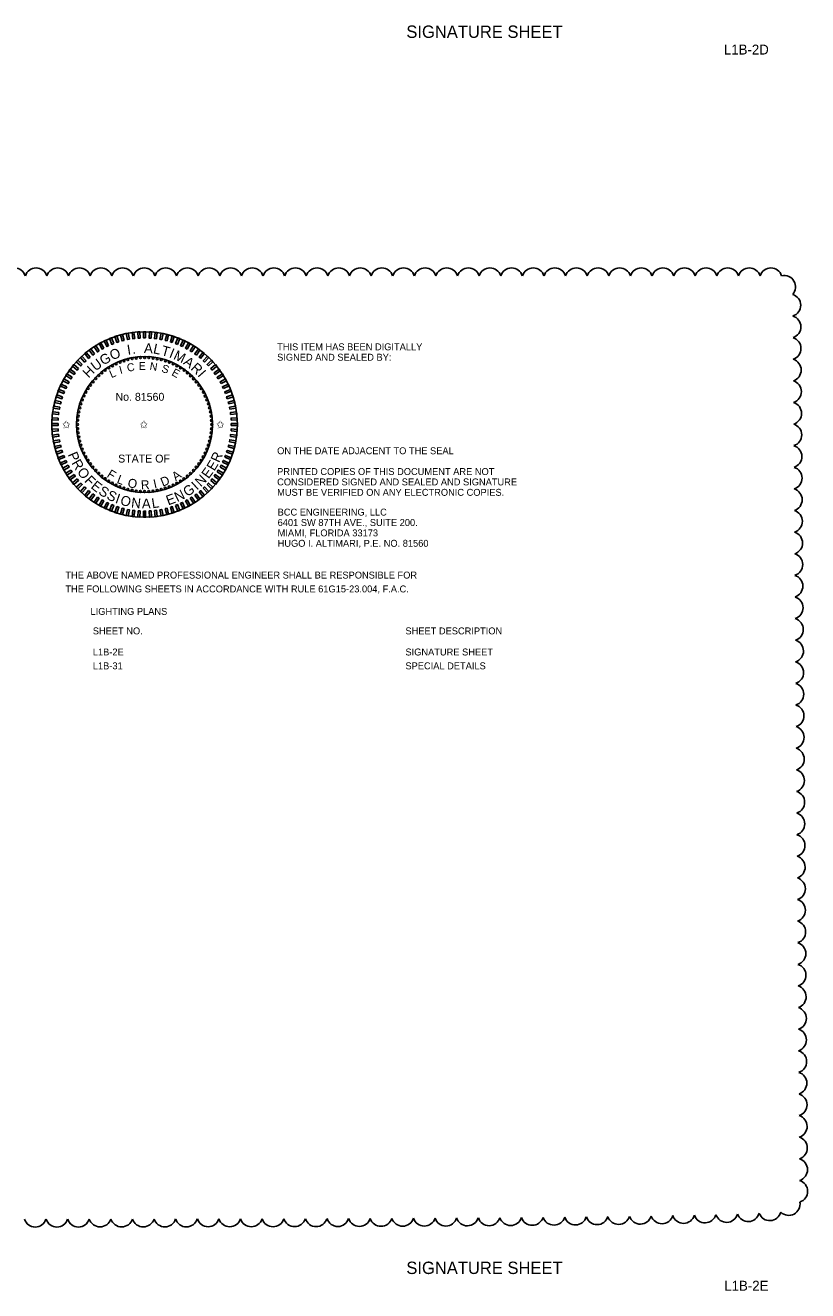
# Model space of a CAD drawing. Extents: x -811.2 to -795, y -2307.6 to -2235.1.
# Drawn here: x -803.05 to -795.14, y -2307.64 to -2294.86 of the extents above; entities that cross this region are included whole.
import ezdxf

# ---------------------------------------------------------------- set-up
doc = ezdxf.new("R2010")
doc.units = 0
for name, color, linetype in [('Cloud_dp', 7, 'Continuous'), ('Logo_dp', 7, 'Continuous'), ('NonPlottingEle_dp', 7, 'Continuous'), ('TeleMisc', 7, 'Continuous'), ('TextDetails', 7, 'Continuous'), ('TextMisc', 7, 'Continuous')]:
    doc.layers.add(name, color=color, linetype=linetype)

msp = doc.modelspace()

# ---------------------------------------------------------------- linework, layer by layer
at = {"layer": 'Cloud_dp'}
for centre, start, end in [((-803.157, -2297.421), 17.5, 162.5), ((-802.939, -2297.421), 17.5, 162.5), ((-802.721, -2297.421), 17.5, 162.5), ((-802.502, -2297.421), 17.5, 162.5), ((-802.284, -2297.421), 17.5, 162.5), ((-802.066, -2297.421), 17.5, 162.5), ((-801.847, -2297.421), 17.5, 162.5), ((-801.629, -2297.421), 17.5, 162.5), ((-801.411, -2297.421), 17.5, 162.5), ((-801.192, -2297.421), 17.5, 162.5), ((-800.974, -2297.421), 17.5, 162.5), ((-800.756, -2297.421), 17.5, 162.5), ((-800.537, -2297.421), 17.5, 162.5), ((-800.319, -2297.421), 17.5, 162.5), ((-800.101, -2297.421), 17.5, 162.5), ((-799.882, -2297.421), 17.5, 162.5), ((-799.664, -2297.421), 17.5, 162.5), ((-799.446, -2297.421), 17.5, 162.5), ((-799.227, -2297.421), 17.5, 162.5), ((-799.009, -2297.421), 17.5, 162.5), ((-798.791, -2297.421), 17.5, 162.5), ((-798.572, -2297.421), 17.5, 162.5), ((-798.354, -2297.421), 17.5, 162.5), ((-798.136, -2297.421), 17.5, 162.5), ((-797.917, -2297.421), 17.5, 162.5), ((-797.699, -2297.421), 17.5, 162.5), ((-797.481, -2297.421), 17.5, 162.5), ((-797.262, -2297.421), 17.5, 162.5), ((-797.044, -2297.421), 17.5, 162.5), ((-796.826, -2297.421), 17.5, 162.5), ((-796.607, -2297.421), 17.5, 162.5), ((-796.389, -2297.421), 17.5, 162.5), ((-796.171, -2297.421), 17.5, 162.5), ((-795.952, -2297.421), 17.5, 162.5), ((-795.734, -2297.421), 17.5, 162.5), ((-795.516, -2297.421), 17.5, 162.5), ((-795.381, -2297.498), 318.1116, 103.1116), ((-795.329, -2297.684), 287.9529, 72.9529), ((-795.327, -2297.902), 287.9529, 72.9529), ((-795.326, -2298.121), 287.9529, 72.9529), ((-795.324, -2298.339), 287.9529, 72.9529), ((-795.322, -2298.557), 287.9529, 72.9529), ((-795.32, -2298.776), 287.9529, 72.9529), ((-795.319, -2298.994), 287.9529, 72.9529), ((-795.317, -2299.212), 287.9529, 72.9529), ((-795.315, -2299.431), 287.9529, 72.9529), ((-795.314, -2299.649), 287.9529, 72.9529), ((-795.312, -2299.867), 287.9529, 72.9529), ((-795.31, -2300.086), 287.9529, 72.9529), ((-795.308, -2300.304), 287.9529, 72.9529), ((-795.307, -2300.522), 287.9529, 72.9529), ((-795.305, -2300.741), 287.9529, 72.9529), ((-795.303, -2300.959), 287.9529, 72.9529), ((-795.301, -2301.177), 287.9529, 72.9529), ((-795.3, -2301.395), 287.9529, 72.9529), ((-795.298, -2301.614), 287.9529, 72.9529), ((-795.296, -2301.832), 287.9529, 72.9529), ((-795.295, -2302.05), 287.9529, 72.9529), ((-795.293, -2302.269), 287.9527, 72.9527), ((-795.291, -2302.487), 287.9524, 72.9524), ((-795.289, -2302.705), 287.9521, 72.9521), ((-795.288, -2302.924), 287.9519, 72.9519), ((-795.286, -2303.142), 287.9515, 72.9515), ((-795.284, -2303.36), 287.9512, 72.9512), ((-795.282, -2303.579), 287.9508, 72.9508), ((-795.281, -2303.797), 287.9504, 72.9504), ((-795.279, -2304.015), 287.9499, 72.9499), ((-795.277, -2304.234), 287.9494, 72.9494), ((-795.276, -2304.452), 287.9488, 72.9488), ((-795.274, -2304.67), 287.9481, 72.9481), ((-795.272, -2304.889), 287.9473, 72.9473), ((-795.271, -2305.107), 287.9464, 72.9464), ((-795.269, -2305.325), 287.9452, 72.9452), ((-795.267, -2305.543), 287.9438, 72.9438), ((-795.265, -2305.762), 287.9419, 72.9419), ((-795.264, -2305.98), 287.9394, 72.9394), ((-795.262, -2306.198), 287.9355, 72.9355), ((-795.26, -2306.417), 287.9288, 72.9288), ((-795.259, -2306.635), 287.9106, 72.9106), ((-795.336, -2306.765), 225.4798, 10.4798), ((-802.948, -2306.882), 197.5011, 342.5011), ((-802.729, -2306.882), 197.5111, 342.5111), ((-802.511, -2306.882), 197.522, 342.522), ((-802.293, -2306.881), 197.5335, 342.5335), ((-802.074, -2306.881), 197.5456, 342.5456), ((-801.856, -2306.881), 197.5582, 342.5582), ((-801.638, -2306.881), 197.5715, 342.5715), ((-801.42, -2306.881), 197.5855, 342.5855), ((-801.201, -2306.88), 197.6002, 342.6002), ((-800.983, -2306.88), 197.6157, 342.6157), ((-800.765, -2306.879), 197.6322, 342.6322), ((-800.546, -2306.879), 197.6497, 342.6497), ((-800.328, -2306.878), 197.6683, 342.6683), ((-800.11, -2306.878), 197.6881, 342.6881), ((-799.891, -2306.877), 197.7093, 342.7093), ((-799.673, -2306.876), 197.732, 342.732), ((-799.455, -2306.875), 197.7565, 342.7565), ((-799.236, -2306.874), 197.7829, 342.7829), ((-799.018, -2306.873), 197.8116, 342.8116), ((-798.8, -2306.872), 197.8429, 342.8429), ((-798.582, -2306.87), 197.8771, 342.8771), ((-798.363, -2306.869), 197.9149, 342.9149), ((-798.145, -2306.867), 197.9569, 342.9569), ((-797.927, -2306.865), 198.0039, 343.0039), ((-797.708, -2306.863), 198.0569, 343.0569), ((-797.49, -2306.861), 198.1174, 343.1174), ((-797.272, -2306.858), 198.1874, 343.1874), ((-797.054, -2306.856), 198.2696, 343.2696), ((-796.835, -2306.853), 198.368, 343.368), ((-796.617, -2306.849), 198.4888, 343.4888), ((-796.399, -2306.845), 198.642, 343.642), ((-796.181, -2306.84), 198.8454, 343.8454), ((-795.963, -2306.835), 199.1345, 344.1345), ((-795.745, -2306.827), 199.5943, 344.5943), ((-795.527, -2306.818), 200.5167, 345.5167)]:
    msp.add_arc(centre, 0.114, start, end, dxfattribs=at)
at = {"layer": 'TextDetails'}
for radius in [0.937, 0.687]:
    msp.add_circle((-801.843, -2298.889), radius, dxfattribs=at)
at = {"layer": 'TextMisc'}
for p, q in [((-801.853, -2299.826), (-801.853, -2299.763)), ((-801.843, -2299.826), (-801.843, -2299.763)), ((-801.833, -2299.826), (-801.833, -2299.763))]:
    msp.add_line(p, q, dxfattribs=at)
for points in [[(-801.997, -2298.028), (-802.016, -2298.031), (-802.028, -2297.97), (-802.008, -2297.966)], [(-801.942, -2298.02), (-801.962, -2298.022), (-801.97, -2297.96), (-801.95, -2297.958)], [(-801.887, -2298.015), (-801.908, -2298.016), (-801.912, -2297.954), (-801.891, -2297.953)], [(-801.833, -2298.014), (-801.853, -2298.014), (-801.853, -2297.952), (-801.833, -2297.952)], [(-801.778, -2298.016), (-801.798, -2298.015), (-801.794, -2297.953), (-801.774, -2297.954)], [(-801.723, -2298.022), (-801.743, -2298.02), (-801.735, -2297.958), (-801.715, -2297.96)], [(-801.669, -2298.032), (-801.689, -2298.028), (-801.677, -2297.966), (-801.657, -2297.97)], [(-802.303, -2298.145), (-802.32, -2298.156), (-802.353, -2298.103), (-802.336, -2298.092)], [(-802.255, -2298.117), (-802.273, -2298.127), (-802.303, -2298.072), (-802.285, -2298.063)], [(-802.206, -2298.093), (-802.224, -2298.102), (-802.251, -2298.045), (-802.232, -2298.037)], [(-802.155, -2298.072), (-802.174, -2298.079), (-802.197, -2298.021), (-802.178, -2298.014)], [(-802.103, -2298.054), (-802.122, -2298.06), (-802.142, -2298.001), (-802.123, -2297.994)], [(-802.05, -2298.039), (-802.07, -2298.044), (-802.085, -2297.984), (-802.066, -2297.979)], [(-801.615, -2298.044), (-801.635, -2298.039), (-801.619, -2297.979), (-801.6, -2297.984)], [(-801.563, -2298.06), (-801.582, -2298.054), (-801.563, -2297.994), (-801.543, -2298.001)], [(-801.511, -2298.079), (-801.53, -2298.072), (-801.507, -2298.014), (-801.488, -2298.021)], [(-801.461, -2298.102), (-801.479, -2298.093), (-801.453, -2298.037), (-801.434, -2298.045)], [(-801.412, -2298.127), (-801.43, -2298.117), (-801.4, -2298.063), (-801.382, -2298.073)], [(-801.365, -2298.156), (-801.382, -2298.145), (-801.349, -2298.092), (-801.332, -2298.103)], [(-802.434, -2298.244), (-802.449, -2298.258), (-802.491, -2298.213), (-802.477, -2298.199)], [(-802.392, -2298.208), (-802.408, -2298.221), (-802.448, -2298.173), (-802.432, -2298.16)], [(-802.349, -2298.175), (-802.365, -2298.187), (-802.402, -2298.137), (-802.385, -2298.125)], [(-801.32, -2298.187), (-801.337, -2298.175), (-801.3, -2298.125), (-801.284, -2298.137)], [(-801.277, -2298.221), (-801.293, -2298.208), (-801.253, -2298.16), (-801.238, -2298.173)], [(-801.237, -2298.258), (-801.251, -2298.244), (-801.208, -2298.199), (-801.194, -2298.213)], [(-802.544, -2298.366), (-802.556, -2298.383), (-802.607, -2298.346), (-802.595, -2298.33)], [(-802.51, -2298.323), (-802.523, -2298.339), (-802.571, -2298.299), (-802.558, -2298.284)], [(-802.473, -2298.283), (-802.487, -2298.297), (-802.533, -2298.255), (-802.519, -2298.24)], [(-801.198, -2298.297), (-801.212, -2298.283), (-801.166, -2298.24), (-801.153, -2298.255)], [(-801.162, -2298.339), (-801.175, -2298.324), (-801.127, -2298.284), (-801.114, -2298.299)], [(-801.129, -2298.383), (-801.141, -2298.367), (-801.09, -2298.33), (-801.079, -2298.346)], [(-802.63, -2298.507), (-802.638, -2298.525), (-802.695, -2298.499), (-802.686, -2298.481)], [(-802.604, -2298.458), (-802.614, -2298.476), (-802.669, -2298.446), (-802.659, -2298.428)], [(-802.576, -2298.412), (-802.587, -2298.429), (-802.639, -2298.395), (-802.628, -2298.378)], [(-801.099, -2298.429), (-801.11, -2298.412), (-801.057, -2298.378), (-801.046, -2298.395)], [(-801.071, -2298.476), (-801.081, -2298.459), (-801.026, -2298.429), (-801.017, -2298.446)], [(-801.047, -2298.526), (-801.056, -2298.507), (-800.999, -2298.481), (-800.99, -2298.499)], [(-802.671, -2298.609), (-802.678, -2298.628), (-802.737, -2298.609), (-802.731, -2298.59)], [(-802.652, -2298.557), (-802.66, -2298.576), (-802.718, -2298.553), (-802.71, -2298.534)], [(-801.026, -2298.576), (-801.033, -2298.558), (-800.975, -2298.535), (-800.968, -2298.553)], [(-801.008, -2298.628), (-801.014, -2298.609), (-800.955, -2298.59), (-800.948, -2298.609)], [(-802.7, -2298.715), (-802.704, -2298.735), (-802.765, -2298.723), (-802.761, -2298.703)], [(-802.687, -2298.661), (-802.692, -2298.681), (-802.753, -2298.665), (-802.748, -2298.646)], [(-800.993, -2298.681), (-800.998, -2298.662), (-800.938, -2298.646), (-800.932, -2298.666)], [(-800.982, -2298.735), (-800.985, -2298.715), (-800.924, -2298.703), (-800.92, -2298.723)], [(-802.715, -2298.824), (-802.716, -2298.844), (-802.779, -2298.84), (-802.777, -2298.82)], [(-802.709, -2298.769), (-802.712, -2298.789), (-802.774, -2298.781), (-802.771, -2298.761)], [(-800.974, -2298.789), (-800.976, -2298.769), (-800.914, -2298.761), (-800.912, -2298.781)], [(-800.969, -2298.844), (-800.97, -2298.824), (-800.908, -2298.82), (-800.907, -2298.84)], [(-802.717, -2298.879), (-802.717, -2298.899), (-802.78, -2298.899), (-802.78, -2298.879)], [(-802.716, -2298.934), (-802.715, -2298.954), (-802.777, -2298.958), (-802.779, -2298.937)], [(-802.712, -2298.988), (-802.709, -2299.008), (-802.771, -2299.016), (-802.774, -2298.996)], [(-800.976, -2299.009), (-800.974, -2298.989), (-800.912, -2298.996), (-800.914, -2299.016)], [(-800.97, -2298.954), (-800.969, -2298.934), (-800.907, -2298.938), (-800.908, -2298.958)], [(-800.968, -2298.899), (-800.968, -2298.879), (-800.906, -2298.879), (-800.906, -2298.899)], [(-802.704, -2299.043), (-802.7, -2299.063), (-802.761, -2299.074), (-802.765, -2299.054)], [(-802.692, -2299.096), (-802.687, -2299.116), (-802.748, -2299.132), (-802.753, -2299.112)], [(-800.998, -2299.116), (-800.993, -2299.097), (-800.933, -2299.112), (-800.938, -2299.132)], [(-800.985, -2299.063), (-800.982, -2299.043), (-800.92, -2299.055), (-800.924, -2299.074)], [(-802.678, -2299.149), (-802.671, -2299.169), (-802.731, -2299.188), (-802.737, -2299.169)], [(-802.66, -2299.201), (-802.652, -2299.22), (-802.71, -2299.243), (-802.718, -2299.224)], [(-802.638, -2299.252), (-802.63, -2299.27), (-802.686, -2299.297), (-802.695, -2299.279)], [(-801.056, -2299.27), (-801.047, -2299.252), (-800.991, -2299.279), (-800.999, -2299.297)], [(-801.033, -2299.22), (-801.026, -2299.201), (-800.968, -2299.224), (-800.975, -2299.243)], [(-801.014, -2299.169), (-801.008, -2299.15), (-800.948, -2299.169), (-800.955, -2299.188)], [(-802.614, -2299.301), (-802.604, -2299.319), (-802.659, -2299.349), (-802.669, -2299.331)], [(-802.587, -2299.349), (-802.576, -2299.366), (-802.629, -2299.399), (-802.639, -2299.382)], [(-801.11, -2299.366), (-801.099, -2299.349), (-801.046, -2299.382), (-801.057, -2299.4)], [(-801.081, -2299.319), (-801.071, -2299.301), (-801.017, -2299.331), (-801.026, -2299.349)], [(-802.556, -2299.395), (-802.544, -2299.411), (-802.595, -2299.448), (-802.607, -2299.431)], [(-802.523, -2299.438), (-802.51, -2299.454), (-802.558, -2299.494), (-802.571, -2299.478)], [(-802.487, -2299.48), (-802.473, -2299.495), (-802.519, -2299.538), (-802.533, -2299.523)], [(-801.212, -2299.495), (-801.198, -2299.48), (-801.153, -2299.523), (-801.167, -2299.538)], [(-801.175, -2299.454), (-801.162, -2299.439), (-801.114, -2299.478), (-801.127, -2299.494)], [(-801.141, -2299.411), (-801.129, -2299.395), (-801.079, -2299.432), (-801.091, -2299.448)], [(-802.449, -2299.519), (-802.434, -2299.533), (-802.477, -2299.579), (-802.492, -2299.565)], [(-802.408, -2299.556), (-802.393, -2299.569), (-802.432, -2299.617), (-802.448, -2299.604)], [(-802.365, -2299.59), (-802.349, -2299.602), (-802.385, -2299.653), (-802.402, -2299.641)], [(-802.32, -2299.622), (-802.303, -2299.633), (-802.336, -2299.685), (-802.353, -2299.675)], [(-801.383, -2299.633), (-801.366, -2299.622), (-801.332, -2299.675), (-801.349, -2299.685)], [(-801.337, -2299.602), (-801.32, -2299.591), (-801.284, -2299.641), (-801.3, -2299.653)], [(-801.293, -2299.569), (-801.277, -2299.556), (-801.238, -2299.604), (-801.253, -2299.617)], [(-801.251, -2299.533), (-801.237, -2299.52), (-801.194, -2299.565), (-801.209, -2299.579)], [(-802.273, -2299.65), (-802.255, -2299.66), (-802.285, -2299.715), (-802.303, -2299.705)], [(-802.224, -2299.676), (-802.206, -2299.684), (-802.233, -2299.741), (-802.251, -2299.732)], [(-802.174, -2299.698), (-802.155, -2299.706), (-802.178, -2299.764), (-802.197, -2299.756)], [(-802.123, -2299.718), (-802.103, -2299.724), (-802.123, -2299.783), (-802.142, -2299.777)], [(-802.07, -2299.733), (-802.051, -2299.738), (-802.066, -2299.799), (-802.086, -2299.794)], [(-802.017, -2299.746), (-801.997, -2299.75), (-802.008, -2299.811), (-802.028, -2299.807)], [(-801.962, -2299.755), (-801.942, -2299.758), (-801.95, -2299.82), (-801.97, -2299.817)], [(-801.908, -2299.761), (-801.888, -2299.762), (-801.892, -2299.825), (-801.912, -2299.823)], [(-801.853, -2299.763), (-801.833, -2299.763), (-801.833, -2299.826), (-801.853, -2299.826)], [(-801.798, -2299.762), (-801.778, -2299.761), (-801.774, -2299.823), (-801.794, -2299.825)], [(-801.743, -2299.758), (-801.723, -2299.755), (-801.715, -2299.817), (-801.735, -2299.82)], [(-801.689, -2299.75), (-801.669, -2299.746), (-801.657, -2299.807), (-801.677, -2299.811)], [(-801.635, -2299.739), (-801.615, -2299.734), (-801.6, -2299.794), (-801.619, -2299.799)], [(-801.582, -2299.724), (-801.563, -2299.718), (-801.544, -2299.777), (-801.563, -2299.783)], [(-801.53, -2299.706), (-801.511, -2299.698), (-801.488, -2299.756), (-801.507, -2299.764)], [(-801.479, -2299.685), (-801.461, -2299.676), (-801.435, -2299.732), (-801.453, -2299.741)], [(-801.43, -2299.66), (-801.413, -2299.65), (-801.382, -2299.705), (-801.4, -2299.715)]]:
    msp.add_lwpolyline(points, close=True, dxfattribs=at)
for centre in [(-802.011, -2298.233), (-801.969, -2298.223), (-801.927, -2298.217), (-801.885, -2298.213), (-801.842, -2298.212), (-801.8, -2298.213), (-801.757, -2298.217), (-801.715, -2298.224), (-801.674, -2298.233), (-802.274, -2298.367), (-802.24, -2298.341), (-802.205, -2298.317), (-802.168, -2298.295), (-802.131, -2298.276), (-802.091, -2298.259), (-802.051, -2298.245), (-801.633, -2298.245), (-801.593, -2298.259), (-801.554, -2298.276), (-801.516, -2298.296), (-801.479, -2298.317), (-801.444, -2298.341), (-801.411, -2298.367), (-802.39, -2298.49), (-802.364, -2298.457), (-802.336, -2298.425), (-802.306, -2298.395), (-801.379, -2298.396), (-801.349, -2298.426), (-801.321, -2298.458), (-801.294, -2298.491), (-802.455, -2298.6), (-802.436, -2298.562), (-802.414, -2298.525), (-801.271, -2298.526), (-801.249, -2298.563), (-801.23, -2298.601), (-802.498, -2298.72), (-802.487, -2298.679), (-802.472, -2298.639), (-801.213, -2298.64), (-801.198, -2298.68), (-801.187, -2298.721), (-802.519, -2298.846), (-802.514, -2298.803), (-802.508, -2298.761), (-801.177, -2298.762), (-801.171, -2298.804), (-801.167, -2298.847), (-802.52, -2298.888), (-802.519, -2298.931), (-802.515, -2298.973), (-801.171, -2298.974), (-801.167, -2298.932), (-801.165, -2298.889), (-802.508, -2299.015), (-802.499, -2299.057), (-802.487, -2299.098), (-801.199, -2299.099), (-801.187, -2299.058), (-801.178, -2299.016), (-802.473, -2299.138), (-802.456, -2299.177), (-802.436, -2299.215), (-802.415, -2299.251), (-801.271, -2299.252), (-801.25, -2299.216), (-801.23, -2299.178), (-801.213, -2299.139), (-802.391, -2299.286), (-802.365, -2299.32), (-802.337, -2299.352), (-802.307, -2299.382), (-801.38, -2299.383), (-801.349, -2299.353), (-801.321, -2299.321), (-801.295, -2299.287), (-802.275, -2299.41), (-802.241, -2299.436), (-802.206, -2299.46), (-802.169, -2299.482), (-802.132, -2299.501), (-802.093, -2299.518), (-801.555, -2299.502), (-801.517, -2299.483), (-801.48, -2299.461), (-801.445, -2299.437), (-801.411, -2299.411), (-802.052, -2299.533), (-802.012, -2299.545), (-801.97, -2299.554), (-801.928, -2299.561), (-801.886, -2299.565), (-801.843, -2299.566), (-801.801, -2299.565), (-801.758, -2299.561), (-801.716, -2299.554), (-801.675, -2299.545), (-801.634, -2299.533), (-801.594, -2299.519)]:
    msp.add_circle(centre, 0.01, dxfattribs=at)

# ---------------------------------------------------------------- texts
at = {"layer": 'Logo_dp'}
for s, height, p in [('       SIGNATURE SHEET         ', 0.125, (-799.524, -2294.983)), ('THIS ITEM HAS BEEN DIGITALLY', 0.07, (-800.504, -2298.139)), ('SIGNED AND SEALED BY:', 0.07, (-800.504, -2298.244)), ('No. 81560', 0.08, (-802.137, -2298.649)), ('ON THE DATE ADJACENT TO THE SEAL', 0.07, (-800.504, -2299.189)), ('STATE OF', 0.08, (-802.11, -2299.273)), ('PRINTED COPIES OF THIS DOCUMENT ARE NOT ', 0.07, (-800.504, -2299.399)), ('CONSIDERED SIGNED AND SEALED AND SIGNATURE ', 0.07, (-800.504, -2299.504)), ('MUST BE VERIFIED ON ANY ELECTRONIC COPIES.', 0.07, (-800.504, -2299.609)), ('BCC ENGINEERING, LLC', 0.07, (-800.499, -2299.809)), ('6401 SW 87TH AVE., SUITE 200.', 0.07, (-800.499, -2299.914)), ('MIAMI, FLORIDA 33173', 0.07, (-800.499, -2300.019)), ('HUGO I. ALTIMARI, P.E. NO. 81560', 0.07, (-800.499, -2300.124)), ('THE ABOVE NAMED PROFESSIONAL ENGINEER SHALL BE RESPONSIBLE FOR ', 0.07, (-802.643, -2300.445)), ('THE FOLLOWING SHEETS IN ACCORDANCE WITH RULE 61G15-23.004, F.A.C.', 0.07, (-802.643, -2300.585)), ('LIGHTING PLANS', 0.07, (-802.389, -2300.812)), ('       SIGNATURE SHEET         ', 0.125, (-799.524, -2307.471))]:
    msp.add_text(s, height=height, dxfattribs=at).set_placement(p)
for s, height, rotation, p in [('I', 0.1, 8.9826, (-802.012, -2298.185)), ('A', 0.1, 356.8926, (-801.851, -2298.166)), ('L', 0.1, 347.4752, (-801.762, -2298.168)), ('T', 0.1, 344.2727, (-801.682, -2298.185)), ('U', 0.1, 36.7249, (-802.339, -2298.354)), ('G', 0.1, 28.7821, (-802.263, -2298.294)), ('O', 0.1, 23.3052, (-802.17, -2298.242)), ('.', 0.1, 6.0117, (-801.965, -2298.176)), ('I', 0.1, 337.7777, (-801.602, -2298.207)), ('M', 0.1, 334.487, (-801.559, -2298.224)), ('A', 0.1, 324.4537, (-801.459, -2298.274)), ('H', 0.1, 44.3421, (-802.409, -2298.426)), ('R', 0.1, 317.6422, (-801.383, -2298.328)), ('I', 0.1, 310.7442, (-801.313, -2298.392)), ('P', 0.1, 293.1955, (-802.621, -2299.191)), ('R', 0.1, 300.2595, (-802.584, -2299.277)), ('E', 0.1, 58.6169, (-801.139, -2299.365)), ('R', 0.1, 65.2886, (-801.09, -2299.281)), ('O', 0.1, 307.2662, (-802.53, -2299.369)), ('F', 0.09, 328.534, (-802.231, -2299.414)), ('A', 0.09, 35.5463, (-801.528, -2299.464)), ('E', 0.1, 53.9986, (-801.196, -2299.443)), ('F', 0.1, 314.2033, (-802.457, -2299.462)), ('E', 0.1, 321.0594, (-802.393, -2299.525)), ('L', 0.09, 339.4875, (-802.13, -2299.477)), ('O', 0.09, 348.0816, (-802.02, -2299.518)), ('R', 0.09, 3.1074, (-801.878, -2299.544)), ('I', 0.09, 12.5248, (-801.744, -2299.535)), ('D', 0.09, 22.2223, (-801.66, -2299.518)), ('G', 0.1, 34.1136, (-801.412, -2299.623)), ('I', 0.1, 41.8391, (-801.315, -2299.557)), ('N', 0.1, 44.3421, (-801.276, -2299.523)), ('S', 0.1, 327.8239, (-802.317, -2299.586)), ('S', 0.1, 334.487, (-802.234, -2299.637)), ('I', 0.1, 341.04, (-802.146, -2299.678)), ('O', 0.1, 344.2727, (-802.096, -2299.696)), ('N', 0.1, 353.7858, (-801.982, -2299.726)), ('L', 0.1, 8.9826, (-801.764, -2299.736)), ('E', 0.1, 20.5125, (-801.604, -2299.707)), ('N', 0.1, 26.0618, (-801.513, -2299.674)), ('A', 0.1, 359.9662, (-801.87, -2299.737))]:
    msp.add_text(s, height=height, rotation=rotation, dxfattribs=at).set_placement(p)
at = {"layer": 'NonPlottingEle_dp'}
for s, p in [('L1B-2D ', (-795.991, -2295.151)), ('L1B-2E ', (-795.987, -2307.639))]:
    msp.add_text(s, height=0.1, dxfattribs=at).set_placement(p)
at = {"layer": 'TeleMisc'}
for s, p in [('SHEET NO.', (-802.366, -2301.009)), ('SHEET DESCRIPTION', (-799.208, -2301.009)), ('L1B-2E', (-802.366, -2301.222)), ('SIGNATURE SHEET', (-799.208, -2301.222)), ('L1B-31', (-802.366, -2301.362)), ('SPECIAL DETAILS', (-799.208, -2301.362))]:
    msp.add_text(s, height=0.07, dxfattribs=at).set_placement(p)
at = {"layer": 'TextMisc'}
for s, rotation, p in [('L', 23.3052, (-802.178, -2298.421)), ('I', 14.8189, (-802.088, -2298.379)), ('C', 8.9826, (-802.015, -2298.356)), ('E', 359.9662, (-801.903, -2298.337)), ('N', 350.6464, (-801.796, -2298.336)), ('S', 341.04, (-801.679, -2298.354)), ('E', 331.1686, (-801.577, -2298.387))]:
    msp.add_text(s, height=0.08, rotation=rotation, dxfattribs=at).set_placement(p)
for p in [(-802.677, -2298.927), (-801.893, -2298.927), (-801.121, -2298.927)]:
    msp.add_text('✩', height=0.08, dxfattribs=at).set_placement(p)

doc.saveas('drawing.dxf')
